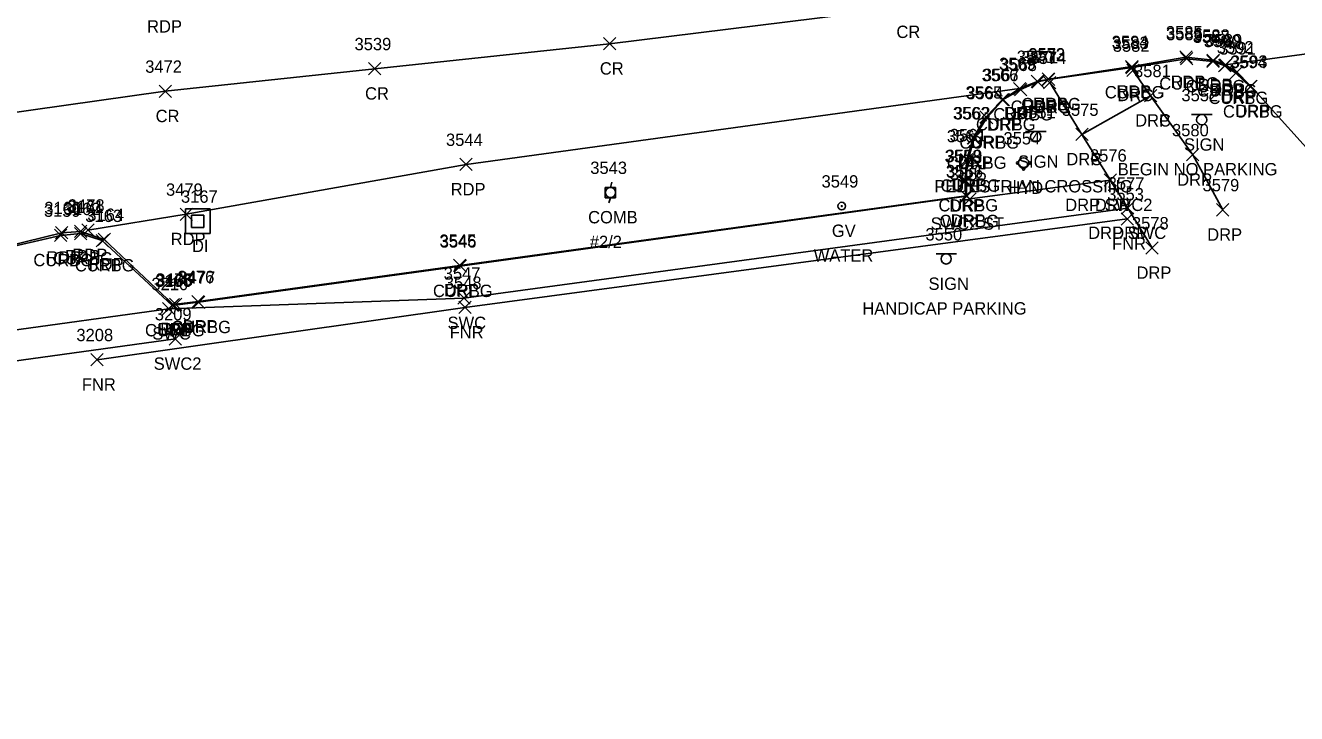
# Model space of a CAD drawing. Extents: x 1690689 to 1696275, y 438760 to 444007.
# Drawn here: x 1691252.6 to 1691458.4, y 442311.5 to 442422.9 of the extents above; entities that cross this region are included whole.
import ezdxf

# ---------------------------------------------------------------- set-up
doc = ezdxf.new("R2010")
doc.units = 0
for name, color, linetype in [('D_A', 7, 'Continuous'), ('D_I', 7, 'Continuous'), ('DS', 7, 'Continuous'), ('L_A', 7, 'Continuous'), ('L_I', 7, 'Continuous'), ('L_TIC', 7, 'Continuous'), ('LFNC', 7, 'Continuous'), ('P_A', 7, 'Continuous'), ('P_I', 7, 'Continuous'), ('P_TIC', 7, 'Continuous'), ('PET', 7, 'Continuous'), ('PRC', 7, 'Continuous'), ('R_A', 7, 'Continuous'), ('R_I', 7, 'Continuous'), ('R_TIC', 7, 'Continuous'), ('RC', 7, 'Continuous'), ('RDP', 7, 'Continuous'), ('RSW', 7, 'Continuous'), ('S_A', 7, 'Continuous'), ('S_C', 7, 'Continuous'), ('S_I', 7, 'Continuous'), ('SSGN', 7, 'Continuous'), ('U_A', 7, 'Continuous'), ('U_C', 7, 'Continuous'), ('U_I', 7, 'Continuous'), ('UP', 7, 'Continuous'), ('UWFH', 7, 'Continuous'), ('UWV', 7, 'Continuous')]:
    doc.layers.add(name, color=color, linetype=linetype)

msp = doc.modelspace()

# ---------------------------------------------------------------- linework, layer by layer
at = {"layer": 'DS'}
for p, q in [((1691278.5, 442393.23), (1691282.5, 442393.23)), ((1691278.5, 442389.23), (1691278.5, 442393.23)), ((1691279.5, 442390.23), (1691279.5, 442392.23)), ((1691279.5, 442392.23), (1691281.5, 442392.23)), ((1691281.5, 442392.23), (1691281.5, 442390.23)), ((1691282.5, 442393.23), (1691282.5, 442389.23)), ((1691281.5, 442390.23), (1691279.5, 442390.23)), ((1691280.51, 442391.23), (1691280.51, 442391.23)), ((1691280.51, 442391.23), (1691280.51, 442391.23)), ((1691282.5, 442389.23), (1691278.5, 442389.23))]:
    msp.add_line(p, q, dxfattribs=at)
at = {"layer": 'L_TIC'}
for points in [[(1691430.01, 442390.61), (1691432.01, 442392.61)], [(1691432.01, 442390.61), (1691430.01, 442392.61)], [(1691322.75, 442376.27), (1691324.75, 442378.27)], [(1691324.75, 442376.27), (1691322.75, 442378.27)], [(1691263.18, 442367.81), (1691265.18, 442369.81)], [(1691265.18, 442367.81), (1691263.18, 442369.81)]]:
    msp.add_lwpolyline(points, dxfattribs=at)
at = {"layer": 'LFNC'}
msp.add_lwpolyline([(1691264.18, 442368.81), (1691323.75, 442377.27), (1691431.01, 442391.61)], dxfattribs=at)
at = {"layer": 'P_TIC'}
for points in [[(1691346.17, 442418.98), (1691348.17, 442420.98)], [(1691348.17, 442418.98), (1691346.17, 442420.98)], [(1691439.51, 442416.83), (1691441.51, 442418.83)], [(1691441.51, 442416.83), (1691439.51, 442418.83)], [(1691308.15, 442414.93), (1691310.15, 442416.93)], [(1691310.15, 442414.93), (1691308.15, 442416.93)], [(1691430.74, 442415.27), (1691432.74, 442417.27)], [(1691432.74, 442415.27), (1691430.74, 442417.27)], [(1691443.91, 442416.31), (1691445.91, 442418.31)], [(1691445.91, 442416.31), (1691443.91, 442418.31)], [(1691445.93, 442415.56), (1691447.93, 442417.56)], [(1691447.93, 442415.56), (1691445.93, 442417.56)], [(1691415.45, 442412.87), (1691417.45, 442414.87)], [(1691417.45, 442412.87), (1691415.45, 442414.87)], [(1691417.24, 442413.27), (1691419.24, 442415.27)], [(1691419.24, 442413.27), (1691417.24, 442415.27)], [(1691274.24, 442411.28), (1691276.24, 442413.28)], [(1691276.24, 442411.28), (1691274.24, 442413.28)], [(1691412.56, 442411.73), (1691414.56, 442413.73)], [(1691414.56, 442411.73), (1691412.56, 442413.73)], [(1691322.95, 442399.43), (1691324.95, 442401.43)], [(1691324.95, 442399.43), (1691322.95, 442401.43)], [(1691277.62, 442391.36), (1691279.62, 442393.36)], [(1691279.62, 442391.36), (1691277.62, 442393.36)], [(1691257.48, 442388.38), (1691259.48, 442390.38)], [(1691259.48, 442388.38), (1691257.48, 442390.38)], [(1691260.52, 442388.58), (1691262.52, 442390.58)], [(1691262.52, 442388.58), (1691260.52, 442390.58)], [(1691261.71, 442388.79), (1691263.71, 442390.79)], [(1691263.71, 442388.79), (1691261.71, 442390.79)], [(1691264.35, 442387.29), (1691266.35, 442389.29)], [(1691266.35, 442387.29), (1691264.35, 442389.29)], [(1691275.53, 442376.73), (1691277.53, 442378.73)], [(1691277.53, 442376.73), (1691275.53, 442378.73)], [(1691275.93, 442376.8), (1691277.93, 442378.8)], [(1691277.93, 442376.8), (1691275.93, 442378.8)]]:
    msp.add_lwpolyline(points, dxfattribs=at)
at = {"layer": 'PET'}
for points in [[(1691262.71, 442389.79), (1691278.62, 442392.36), (1691323.95, 442400.43), (1691413.56, 442412.73), (1691416.45, 442413.87), (1691418.24, 442414.27), (1691431.74, 442416.27), (1691440.51, 442417.83), (1691444.91, 442417.31), (1691446.93, 442416.56), (1691480.01, 442421.07), (1691541.54, 442433.59), (1691592.5, 442446.57), (1691666.55, 442464.92), (1691770.02, 442488.32), (1691794.27, 442493.8), (1691844.9, 442505.22), (1691966.82, 442532.71), (1692001.23, 442540.45), (1692024.42, 442545.45)], [(1691147.42, 442310.3), (1691150.53, 442320.15), (1691154.06, 442329.06), (1691157.38, 442335.47), (1691162.08, 442342.32), (1691168, 442349.27), (1691179.07, 442360.29), (1691185.42, 442365.21), (1691189.67, 442368.02), (1691199.04, 442372.75), (1691205.16, 442375.21), (1691212.79, 442377.84), (1691220.73, 442380.07), (1691237.55, 442384.25), (1691258.48, 442389.38), (1691261.52, 442389.58), (1691265.35, 442388.29), (1691276.53, 442377.73), (1691276.93, 442377.8)]]:
    msp.add_lwpolyline(points, dxfattribs=at)
at = {"layer": 'PRC'}
msp.add_lwpolyline([(1691130.81, 442358.75), (1691152.44, 442373.63), (1691178.23, 442388.18), (1691209.8, 442400.63), (1691248.04, 442408.48), (1691275.24, 442412.28), (1691309.15, 442415.93), (1691347.17, 442419.98), (1691395.19, 442425.91), (1691433.65, 442431.72), (1691478.76, 442438.88), (1691513.2, 442445.49), (1691566.06, 442456.6), (1691813.76, 442512.5), (1691980.06, 442550.02), (1692039.61, 442563.23)], dxfattribs=at)
at = {"layer": 'R_TIC'}
for points in [[(1691430.79, 442415.13), (1691432.79, 442417.13)], [(1691432.79, 442415.13), (1691430.79, 442417.13)], [(1691430.79, 442415.13), (1691432.79, 442417.13)], [(1691432.79, 442415.13), (1691430.79, 442417.13)], [(1691439.61, 442416.55), (1691441.61, 442418.55)], [(1691441.61, 442416.55), (1691439.61, 442418.55)], [(1691443.88, 442416.12), (1691445.88, 442418.12)], [(1691445.88, 442416.12), (1691443.88, 442418.12)], [(1691445.75, 442415.43), (1691447.75, 442417.43)], [(1691447.75, 442415.43), (1691445.75, 442417.43)], [(1691445.93, 442415.56), (1691447.93, 442417.56)], [(1691447.93, 442415.56), (1691445.93, 442417.56)], [(1691415.54, 442412.79), (1691417.54, 442414.79)], [(1691417.54, 442412.79), (1691415.54, 442414.79)], [(1691417.26, 442413.2), (1691419.26, 442415.2)], [(1691419.26, 442413.2), (1691417.26, 442415.2)], [(1691417.26, 442413.2), (1691419.26, 442415.2)], [(1691419.26, 442413.2), (1691417.26, 442415.2)], [(1691417.44, 442412.7), (1691419.44, 442414.7)], [(1691419.44, 442412.7), (1691417.44, 442414.7)], [(1691430.92, 442414.68), (1691432.92, 442416.68)], [(1691432.92, 442414.68), (1691430.92, 442416.68)], [(1691447.59, 442414.22), (1691449.59, 442416.22)], [(1691449.59, 442414.22), (1691447.59, 442416.22)], [(1691447.76, 442414.4), (1691449.76, 442416.4)], [(1691449.76, 442414.4), (1691447.76, 442416.4)], [(1691412.56, 442411.73), (1691414.56, 442413.73)], [(1691414.56, 442411.73), (1691412.56, 442413.73)], [(1691412.73, 442411.56), (1691414.73, 442413.56)], [(1691414.73, 442411.56), (1691412.73, 442413.56)], [(1691449.91, 442412.02), (1691451.91, 442414.02)], [(1691451.91, 442412.02), (1691449.91, 442414.02)], [(1691450.03, 442412.1), (1691452.03, 442414.1)], [(1691452.03, 442412.1), (1691450.03, 442414.1)], [(1691409.79, 442409.91), (1691411.79, 442411.91)], [(1691411.79, 442409.91), (1691409.79, 442411.91)], [(1691409.91, 442409.94), (1691411.91, 442411.94)], [(1691411.91, 442409.94), (1691409.91, 442411.94)], [(1691433.79, 442410.57), (1691435.79, 442412.57)], [(1691435.79, 442410.57), (1691433.79, 442412.57)], [(1691433.79, 442410.57), (1691435.79, 442412.57)], [(1691435.79, 442410.57), (1691433.79, 442412.57)], [(1691407.12, 442407.1), (1691409.12, 442409.1)], [(1691409.12, 442407.1), (1691407.12, 442409.1)], [(1691407.24, 442406.99), (1691409.24, 442408.99)], [(1691409.24, 442406.99), (1691407.24, 442408.99)], [(1691405.06, 442403.73), (1691407.06, 442405.73)], [(1691407.06, 442403.73), (1691405.06, 442405.73)], [(1691405.21, 442403.73), (1691407.21, 442405.73)], [(1691407.21, 442403.73), (1691405.21, 442405.73)], [(1691422.66, 442404.3), (1691424.66, 442406.3)], [(1691424.66, 442404.3), (1691422.66, 442406.3)], [(1691422.66, 442404.3), (1691424.66, 442406.3)], [(1691424.66, 442404.3), (1691422.66, 442406.3)], [(1691440.6, 442400.99), (1691442.6, 442402.99)], [(1691442.6, 442400.99), (1691440.6, 442402.99)], [(1691404, 442400.19), (1691406, 442402.19)], [(1691406, 442400.19), (1691404, 442402.19)], [(1691404.18, 442400.02), (1691406.18, 442402.02)], [(1691406.18, 442400.02), (1691404.18, 442402.02)], [(1691403.69, 442396.77), (1691405.69, 442398.77)], [(1691405.69, 442396.77), (1691403.69, 442398.77)], [(1691403.84, 442396.83), (1691405.84, 442398.83)], [(1691405.84, 442396.83), (1691403.84, 442398.83)], [(1691427.27, 442396.89), (1691429.27, 442398.89)], [(1691429.27, 442396.89), (1691427.27, 442398.89)], [(1691427.27, 442396.89), (1691429.27, 442398.89)], [(1691429.27, 442396.89), (1691427.27, 442398.89)], [(1691403.89, 442394.36), (1691405.89, 442396.36)], [(1691405.89, 442394.36), (1691403.89, 442396.36)], [(1691404, 442394.27), (1691406, 442396.27)], [(1691406, 442394.27), (1691404, 442396.27)], [(1691404.53, 442393.86), (1691406.53, 442395.86)], [(1691406.53, 442393.86), (1691404.53, 442395.86)], [(1691430.09, 442392.37), (1691432.09, 442394.37)], [(1691432.09, 442392.37), (1691430.09, 442394.37)], [(1691430.09, 442392.37), (1691432.09, 442394.37)], [(1691432.09, 442392.37), (1691430.09, 442394.37)], [(1691445.46, 442392.08), (1691447.46, 442394.08)], [(1691447.46, 442392.08), (1691445.46, 442394.08)], [(1691257.28, 442387.95), (1691259.28, 442389.95)], [(1691259.28, 442387.95), (1691257.28, 442389.95)], [(1691260.51, 442388.23), (1691262.51, 442390.23)], [(1691262.51, 442388.23), (1691260.51, 442390.23)], [(1691264.02, 442387.11), (1691266.02, 442389.11)], [(1691266.02, 442387.11), (1691264.02, 442389.11)], [(1691434.02, 442385.91), (1691436.02, 442387.91)], [(1691436.02, 442385.91), (1691434.02, 442387.91)], [(1691321.89, 442383.09), (1691323.89, 442385.09)], [(1691323.89, 442383.09), (1691321.89, 442385.09)], [(1691322, 442382.96), (1691324, 442384.96)], [(1691324, 442382.96), (1691322, 442384.96)], [(1691322.58, 442377.78), (1691324.58, 442379.78)], [(1691324.58, 442377.78), (1691322.58, 442379.78)], [(1691274.77, 442376.07), (1691276.77, 442378.07)], [(1691276.77, 442376.07), (1691274.77, 442378.07)], [(1691275.37, 442376.59), (1691277.37, 442378.59)], [(1691277.37, 442376.59), (1691275.37, 442378.59)], [(1691275.93, 442376.8), (1691277.93, 442378.8)], [(1691277.93, 442376.8), (1691275.93, 442378.8)], [(1691279.54, 442377.22), (1691281.54, 442379.22)], [(1691281.54, 442377.22), (1691279.54, 442379.22)], [(1691279.63, 442377.11), (1691281.63, 442379.11)], [(1691281.63, 442377.11), (1691279.63, 442379.11)], [(1691275.88, 442371.18), (1691277.88, 442373.18)], [(1691277.88, 442371.18), (1691275.88, 442373.18)]]:
    msp.add_lwpolyline(points, dxfattribs=at)
at = {"layer": 'RC'}
for points in [[(1691431.79, 442416.13), (1691440.61, 442417.55), (1691444.88, 442417.12), (1691446.75, 442416.43), (1691448.59, 442415.22), (1691450.91, 442413.02)], [(1691418.26, 442414.2), (1691431.79, 442416.13)], [(1691237.57, 442384.16), (1691258.28, 442388.95), (1691261.51, 442389.23), (1691265.02, 442388.11), (1691276.37, 442377.59), (1691280.63, 442378.11), (1691323, 442383.96), (1691405, 442395.27), (1691404.84, 442397.83), (1691405.18, 442401.02), (1691406.21, 442404.73), (1691408.24, 442407.99), (1691410.91, 442410.94), (1691413.73, 442412.56), (1691416.54, 442413.79), (1691418.26, 442414.2)]]:
    msp.add_lwpolyline(points, dxfattribs=at)
at = {"layer": 'RDP'}
for points in [[(1691418.44, 442413.7), (1691423.66, 442405.3), (1691434.79, 442411.57), (1691431.92, 442415.68)], [(1691446.93, 442416.56), (1691448.76, 442415.4), (1691451.03, 442413.1), (1691463.48, 442399.3)], [(1691276.93, 442377.8), (1691280.54, 442378.22), (1691322.89, 442384.09), (1691404.89, 442395.36), (1691404.69, 442397.77), (1691405, 442401.19), (1691406.06, 442404.73), (1691408.12, 442408.1), (1691410.79, 442410.91), (1691413.56, 442412.73)], [(1691446.46, 442393.08), (1691441.6, 442401.99), (1691434.79, 442411.57)], [(1691423.66, 442405.3), (1691428.27, 442397.89), (1691431.09, 442393.37), (1691435.02, 442386.91)]]:
    msp.add_lwpolyline(points, dxfattribs=at)
at = {"layer": 'RSW'}
for points in [[(1691405.53, 442394.86), (1691428.27, 442397.89)], [(1691173.65, 442147.45), (1691164.24, 442181.45), (1691159.6, 442182.06), (1691158.97, 442186.8), (1691163.01, 442188.55), (1691166.55, 442192.36), (1691154.22, 442268.79), (1691153.3, 442278.85), (1691153.14, 442289.14), (1691154.2, 442299.81), (1691156.14, 442309.64), (1691159.16, 442319.87), (1691163.64, 442329.48), (1691169.43, 442337.95), (1691175.96, 442345.39), (1691184.23, 442352.79), (1691192.51, 442358.59), (1691201.39, 442363.4), (1691210.8, 442367.4), (1691220.98, 442369.51), (1691275.77, 442377.07), (1691323.58, 442378.78), (1691431.09, 442393.37)], [(1691168.85, 442209.69), (1691163.66, 442242.11), (1691162.54, 442249.93), (1691158.99, 442269.5), (1691158.08, 442288.93), (1691158.91, 442298.99), (1691160.84, 442308.68), (1691163.82, 442318.15), (1691167.77, 442326.94), (1691173.26, 442335.01), (1691179.56, 442341.95), (1691187.04, 442348.87), (1691194.85, 442354.29), (1691203.45, 442359.11), (1691212.34, 442362.71), (1691221.77, 442364.59), (1691276.88, 442372.18)]]:
    msp.add_lwpolyline(points, dxfattribs=at)
at = {"layer": 'SSGN'}
for p, q in [((1691441.4, 442408.51), (1691444.73, 442408.51)), ((1691443.05, 442407.68), (1691443.05, 442407.68)), ((1691414.53, 442405.75), (1691417.87, 442405.75)), ((1691416.18, 442404.92), (1691416.18, 442404.92)), ((1691400.04, 442385.98), (1691403.37, 442385.98)), ((1691401.68, 442385.14), (1691401.68, 442385.14))]:
    msp.add_line(p, q, dxfattribs=at)
for centre in [(1691443.05, 442407.68), (1691416.18, 442404.92), (1691401.68, 442385.14)]:
    msp.add_circle(centre, 0.833, dxfattribs=at)
at = {"layer": 'UP'}
for p, q in [((1691346.48, 442395.05), (1691346.48, 442396.72)), ((1691346.48, 442396.72), (1691348.14, 442396.72)), ((1691347.56, 442397.55), (1691347.31, 442396.72)), ((1691348.14, 442396.72), (1691348.14, 442395.05)), ((1691348.14, 442395.05), (1691346.48, 442395.05)), ((1691347.06, 442394.22), (1691347.31, 442395.05)), ((1691347.31, 442395.89), (1691347.31, 442395.89))]:
    msp.add_line(p, q, dxfattribs=at)
msp.add_circle((1691347.31, 442395.89), 0.833, dxfattribs=at)
at = {"layer": 'UWFH'}
msp.add_line((1691414.22, 442400.67), (1691414.22, 442400.67), dxfattribs=at)
for centre, radius in [((1691413.22, 442400.67), 0.167), ((1691414.22, 442400.67), 0.833), ((1691415.22, 442400.67), 0.167), ((1691414.22, 442399.67), 0.167)]:
    msp.add_circle(centre, radius, dxfattribs=at)
at = {"layer": 'UWV'}
for radius in [0.625, 0.0833]:
    msp.add_circle((1691384.77, 442393.69), radius, dxfattribs=at)

# ---------------------------------------------------------------- texts
at = {"layer": 'D_A'}
msp.add_text('DI', height=2, dxfattribs=at).set_placement((1691279.56, 442386.23))
at = {"layer": 'D_I'}
msp.add_text('3167', height=2, dxfattribs=at).set_placement((1691277.77, 442394.23))
at = {"layer": 'L_A'}
for p in [(1691428.55, 442386.61), (1691321.28, 442372.27), (1691261.72, 442363.81)]:
    msp.add_text('FNR', height=2, dxfattribs=at).set_placement(p)
at = {"layer": 'L_I'}
for s, p in [('3553', (1691427.75, 442394.61)), ('3548', (1691320.49, 442380.27)), ('3208', (1691260.84, 442371.81))]:
    msp.add_text(s, height=2, dxfattribs=at).set_placement(p)
at = {"layer": 'P_A'}
for s, p in [('RDP', (1691272.29, 442421.79)), ('CR', (1691393.62, 442420.91)), ('CR', (1691345.6, 442414.98)), ('RDP', (1691438, 442412.83)), ('CR', (1691307.58, 442410.93)), ('RDP', (1691429.22, 442411.27)), ('RDP', (1691442.4, 442412.31)), ('RDP', (1691444.42, 442411.56)), ('RDP', (1691413.94, 442408.87)), ('RDP', (1691415.73, 442409.27)), ('CR', (1691273.67, 442407.28)), ('RDP', (1691411.04, 442407.73)), ('RDP', (1691321.44, 442395.43)), ('RDP', (1691276.11, 442387.36)), ('RDP', (1691255.96, 442384.38)), ('RDP', (1691259.01, 442384.58)), ('RDP', (1691260.2, 442384.79)), ('RDP', (1691262.84, 442383.29)), ('RDP', (1691274.02, 442372.73)), ('RDP', (1691274.42, 442372.8))]:
    msp.add_text(s, height=2, dxfattribs=at).set_placement(p)
at = {"layer": 'P_I'}
for s, p in [('3539', (1691305.88, 442418.93)), ('3584', (1691428.48, 442419.27)), ('3585', (1691437.25, 442420.83)), ('3588', (1691441.65, 442420.31)), ('3589', (1691443.66, 442419.56)), ('3570', (1691413.11, 442416.87)), ('3573', (1691414.98, 442417.27)), ('3472', (1691271.98, 442415.28)), ('3569', (1691410.24, 442415.73)), ('3544', (1691320.69, 442403.43)), ('3479', (1691275.35, 442395.36)), ('3160', (1691255.65, 442392.38)), ('3161', (1691259.35, 442392.58)), ('3478', (1691259.45, 442392.79)), ('3164', (1691262.61, 442391.29)), ('3475', (1691273.67, 442380.8)), ('3165', (1691273.79, 442380.73))]:
    msp.add_text(s, height=2, dxfattribs=at).set_placement(p)
at = {"layer": 'R_A'}
for s, p in [('CURBC', (1691427.37, 442411.13)), ('CURBG', (1691427.37, 442411.13)), ('DRC', (1691429.41, 442410.68)), ('CURBG', (1691436.19, 442412.55)), ('CURBG', (1691440.46, 442412.12)), ('CURBG', (1691442.33, 442411.43)), ('DRP', (1691444.42, 442411.56)), ('CURBG', (1691412.12, 442408.79)), ('CURBG', (1691413.84, 442409.2)), ('CURBC', (1691413.84, 442409.2)), ('DRC', (1691415.93, 442408.7)), ('CURBG', (1691444.17, 442410.22)), ('DRP', (1691446.25, 442410.4)), ('CURBG', (1691409.31, 442407.56)), ('DRP', (1691411.04, 442407.73)), ('DRC', (1691432.28, 442406.57)), ('DRP', (1691432.28, 442406.57)), ('CURBG', (1691446.5, 442408.02)), ('DRP', (1691448.52, 442408.1)), ('CURBG', (1691406.5, 442405.94)), ('DRP', (1691408.28, 442405.91)), ('CURBG', (1691403.82, 442402.99)), ('DRP', (1691405.61, 442403.1)), ('DRC', (1691421.14, 442400.3)), ('DRP', (1691421.14, 442400.3)), ('CURBG', (1691401.79, 442399.73)), ('DRP', (1691403.55, 442399.73)), ('DRP', (1691402.49, 442396.19)), ('DRP', (1691439.09, 442396.99)), ('CURBG', (1691400.76, 442396.02)), ('CURBG', (1691400.43, 442392.83)), ('DRP', (1691402.18, 442392.77)), ('DRP SWC2', (1691420.96, 442392.89)), ('DRP', (1691425.76, 442392.89)), ('CURBG', (1691400.58, 442390.27)), ('DRP', (1691402.38, 442390.36)), ('SWC2 ST', (1691399.17, 442389.86)), ('DRP SWC', (1691424.67, 442388.37)), ('DRP', (1691428.58, 442388.37)), ('DRP', (1691443.95, 442388.08)), ('CURBG', (1691253.87, 442383.95)), ('CURBG', (1691257.09, 442384.23)), ('CURBG', (1691260.6, 442383.11)), ('DRP', (1691432.5, 442381.91)), ('CURBG', (1691318.58, 442378.96)), ('DRP', (1691320.38, 442379.09)), ('SWC', (1691320.94, 442373.78)), ('CURBG', (1691271.95, 442372.59)), ('SWC', (1691273.13, 442372.07)), ('DRP', (1691274.42, 442372.8)), ('CURBG', (1691276.21, 442373.11)), ('DRP', (1691278.03, 442373.22)), ('SWC2', (1691273.36, 442367.18))]:
    msp.add_text(s, height=2, dxfattribs=at).set_placement(p)
at = {"layer": 'R_I'}
for s, p in [('3583', (1691428.53, 442419.13)), ('3583', (1691428.53, 442419.13)), ('3586', (1691437.29, 442420.55)), ('3587', (1691441.62, 442420.12)), ('3590', (1691443.4, 442419.43)), ('3589', (1691443.66, 442419.56)), ('3571', (1691413.85, 442416.79)), ('3572', (1691415, 442417.2)), ('3572', (1691415, 442417.2)), ('3582', (1691428.66, 442418.68)), ('3592', (1691445.5, 442418.4)), ('3591', (1691445.89, 442418.22)), ('3569', (1691410.24, 442415.73)), ('3568', (1691410.42, 442415.56)), ('3574', (1691415.18, 442416.7)), ('3594', (1691447.65, 442416.02)), ('3593', (1691447.77, 442416.1)), ('3566', (1691407.43, 442413.91)), ('3567', (1691407.61, 442413.94)), ('3581', (1691432.1, 442414.57)), ('3581', (1691432.1, 442414.57)), ('3565', (1691404.81, 442411.1)), ('3564', (1691404.93, 442410.99)), ('3562', (1691402.76, 442407.73)), ('3563', (1691402.9, 442407.73)), ('3575', (1691420.4, 442408.3)), ('3575', (1691420.4, 442408.3)), ('3580', (1691438.25, 442404.99)), ('3560', (1691401.79, 442404.02)), ('3561', (1691402.26, 442404.19)), ('3558', (1691401.43, 442400.77)), ('3559', (1691401.58, 442400.83)), ('3576', (1691424.96, 442400.89)), ('3576', (1691424.96, 442400.89)), ('3557', (1691401.63, 442398.36)), ('3556', (1691401.68, 442398.27)), ('3555', (1691402.27, 442397.86)), ('3577', (1691427.83, 442396.37)), ('3577', (1691427.83, 442396.37)), ('3579', (1691443.19, 442396.08)), ('3162', (1691258.77, 442392.23)), ('3159', (1691255.58, 442391.95)), ('3163', (1691262.28, 442391.11)), ('3578', (1691431.76, 442389.91)), ('3545', (1691319.63, 442387.09)), ('3546', (1691319.68, 442386.96)), ('3547', (1691320.32, 442381.78)), ('3210', (1691272.99, 442380.07)), ('3166', (1691273.58, 442380.59)), ('3475', (1691273.67, 442380.8)), ('3476', (1691277.22, 442381.22)), ('3477', (1691277.37, 442381.11)), ('3209', (1691273.54, 442375.18))]:
    msp.add_text(s, height=2, dxfattribs=at).set_placement(p)
at = {"layer": 'S_A'}
for p in [(1691440.19, 442402.66), (1691413.32, 442399.9), (1691398.82, 442380.12)]:
    msp.add_text('SIGN', height=2, dxfattribs=at).set_placement(p)
at = {"layer": 'S_C'}
for s, p in [('BEGIN NO PARKING', (1691429.46, 442398.66)), ('PEDESTRIAN CROSSING', (1691399.76, 442395.9)), ('HANDICAP PARKING', (1691388.1, 442376.12))]:
    msp.add_text(s, height=2, dxfattribs=at).set_placement(p)
at = {"layer": 'S_I'}
for s, p in [('3552', (1691439.77, 442410.66)), ('3551', (1691413.47, 442407.9)), ('3550', (1691398.32, 442388.12))]:
    msp.add_text(s, height=2, dxfattribs=at).set_placement(p)
at = {"layer": 'U_A'}
for s, p in [('HYD', (1691411.74, 442395.67)), ('COMB', (1691343.7, 442390.89)), ('GV', (1691383.17, 442388.69))]:
    msp.add_text(s, height=2, dxfattribs=at).set_placement(p)
at = {"layer": 'U_C'}
for s, p in [('#2/2', (1691343.97, 442386.89)), ('WATER', (1691380.23, 442384.69))]:
    msp.add_text(s, height=2, dxfattribs=at).set_placement(p)
at = {"layer": 'U_I'}
for s, p in [('3554', (1691410.96, 442403.67)), ('3543', (1691344.05, 442398.89)), ('3549', (1691381.5, 442396.69))]:
    msp.add_text(s, height=2, dxfattribs=at).set_placement(p)

doc.saveas('drawing.dxf')
